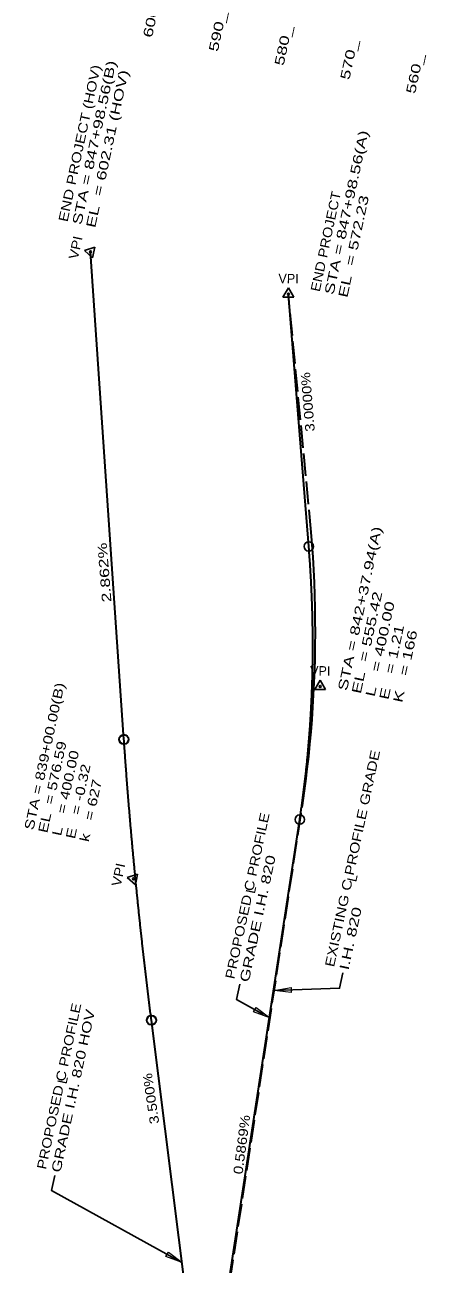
# Model space of a CAD drawing. Extents: x 2363411 to 2369702, y 6977197 to 6988655.
# Drawn here: x 2367365 to 2367963, y 6983553 to 6985397 of the extents above; entities that cross this region are included whole.
import ezdxf
from ezdxf.enums import TextEntityAlignment as Align

# ---------------------------------------------------------------- set-up
doc = ezdxf.new("R2010")
doc.units = 0
doc.header["$LTSCALE"] = 5.6
doc.linetypes.add('LONG_DASHED', pattern=[7.5, 6, -1.5])
for name, color, linetype, lineweight in [('44', 7, 'Continuous', 25), ('58', 7, 'Continuous', 25), ('61', 7, 'Continuous', 25)]:
    doc.layers.add(name, color=color, linetype=linetype, lineweight=lineweight)
doc.layers.add('50', color=7, linetype='Continuous')

msp = doc.modelspace()

# ---------------------------------------------------------------- linework, layer by layer
at = {"layer": '44'}
for p, q in [((2367454.227, 6985060.892), (2367469.602, 6985065.858)), ((2367466.212, 6985050.057), (2367469.602, 6985065.858)), ((2367454.227, 6985060.892), (2367466.212, 6985050.057)), ((2367757.608, 6985005.409), (2367749.412, 6984991.485)), ((2367749.412, 6984991.485), (2367765.572, 6984991.35)), ((2367757.608, 6985005.409), (2367765.572, 6984991.35)), ((2367804.816, 6984422.007), (2367796.685, 6984408.047)), ((2367804.816, 6984422.007), (2367812.845, 6984407.989)), ((2367796.685, 6984408.047), (2367812.845, 6984407.989))]:
    msp.add_line(p, q, dxfattribs=at)
at = {"layer": '44', "lineweight": 35}
for p, q in [((2367512.9, 6984334.011), (2367463.348, 6985058.925)), ((2367787.84, 6984620.829), (2367757.481, 6984996.078)), ((2367604.934, 6983107.709), (2367774.368, 6984214.683)), ((2367609.745, 6983474.807), (2367553.751, 6983916.249))]:
    msp.add_line(p, q, dxfattribs=at)
at = {"layer": '44', "linetype": 'LONG_DASHED', "lineweight": 35}
for points in [[(2367778.265, 6984235.836), (2367780.917, 6984253.937), (2367783.373, 6984272.077), (2367785.633, 6984290.26), (2367787.697, 6984308.486), (2367789.566, 6984326.753), (2367791.24, 6984345.062), (2367792.718, 6984363.412), (2367794, 6984381.804), (2367795.087, 6984400.238), (2367795.977, 6984418.714), (2367796.647, 6984436.432), (2367796.647, 6984436.432), (2367797.155, 6984454.991), (2367797.469, 6984473.591), (2367797.585, 6984492.232), (2367797.507, 6984510.916), (2367797.232, 6984529.641), (2367796.763, 6984548.409), (2367796.098, 6984567.218), (2367795.237, 6984586.067), (2367794.181, 6984604.96), (2367792.929, 6984623.894), (2367791.548, 6984642.045), (2367757.52, 6984996.07)], [(2367626.232, 6983236.018), (2367778.265, 6984235.836), (2367778.265, 6984235.836)]]:
    msp.add_lwpolyline(points, dxfattribs=at)
at = {"layer": '44'}
for centre, radius in [((2367463.348, 6985058.925), 1.5), ((2367757.521, 6984996.078), 1.5), ((2367787.837, 6984620.83), 7), ((2367804.772, 6984412.677), 1.5), ((2367774.364, 6984214.684), 7)]:
    msp.add_circle(centre, radius, dxfattribs=at)
at = {"layer": '44', "lineweight": 35}
for centre in [(2367512.899, 6984334.012), (2367553.751, 6983916.249)]:
    msp.add_circle(centre, 7, dxfattribs=at)
for points in [[(2367774.368, 6984214.683), (2367775.56, 6984222.609), (2367776.718, 6984230.542), (2367777.836, 6984238.484), (2367778.915, 6984246.434), (2367779.959, 6984254.391), (2367780.963, 6984262.357), (2367781.93, 6984270.329), (2367782.861, 6984278.311), (2367783.752, 6984286.301), (2367784.606, 6984294.299), (2367785.423, 6984302.305), (2367786.201, 6984310.32), (2367786.941, 6984318.342), (2367787.645, 6984326.372), (2367788.311, 6984334.41), (2367788.938, 6984342.457), (2367789.528, 6984350.511), (2367790.081, 6984358.574), (2367790.595, 6984366.645), (2367791.073, 6984374.723), (2367791.511, 6984382.81), (2367791.913, 6984390.905), (2367792.276, 6984399.008), (2367792.602, 6984407.119), (2367792.891, 6984415.238), (2367793.143, 6984423.364), (2367793.355, 6984431.5), (2367793.531, 6984439.643), (2367793.667, 6984447.794), (2367793.768, 6984455.953), (2367793.83, 6984464.12), (2367793.853, 6984472.296), (2367793.841, 6984480.479), (2367793.789, 6984488.671), (2367793.7, 6984496.87), (2367793.575, 6984505.078), (2367793.41, 6984513.294), (2367793.208, 6984521.518), (2367792.968, 6984529.749), (2367792.69, 6984537.989), (2367792.374, 6984546.237), (2367792.022, 6984554.493), (2367791.632, 6984562.757), (2367791.202, 6984571.027), (2367790.736, 6984579.308), (2367790.233, 6984587.596), (2367789.691, 6984595.892), (2367789.113, 6984604.196), (2367788.496, 6984612.508), (2367787.84, 6984620.829)], [(2367553.751, 6983916.249), (2367552.689, 6983924.657), (2367551.638, 6983933.062), (2367550.597, 6983941.465), (2367549.565, 6983949.866), (2367548.544, 6983958.265), (2367547.532, 6983966.662), (2367546.53, 6983975.056), (2367545.538, 6983983.449), (2367544.555, 6983991.839), (2367543.584, 6984000.227), (2367542.621, 6984008.614), (2367541.67, 6984016.998), (2367540.729, 6984025.381), (2367539.798, 6984033.761), (2367538.876, 6984042.138), (2367537.964, 6984050.514), (2367537.061, 6984058.887), (2367536.169, 6984067.259), (2367535.288, 6984075.627), (2367534.415, 6984083.994), (2367533.554, 6984092.359), (2367532.703, 6984100.722), (2367531.861, 6984109.082), (2367531.027, 6984117.441), (2367530.205, 6984125.797), (2367529.395, 6984134.151), (2367528.592, 6984142.503), (2367527.799, 6984150.853), (2367527.018, 6984159.2), (2367526.245, 6984167.546), (2367525.484, 6984175.889), (2367524.732, 6984184.23), (2367523.988, 6984192.57), (2367523.256, 6984200.907), (2367522.534, 6984209.242), (2367521.823, 6984217.574), (2367521.12, 6984225.905), (2367520.428, 6984234.236), (2367519.746, 6984242.562), (2367519.073, 6984250.886), (2367518.411, 6984259.208), (2367517.759, 6984267.528), (2367517.117, 6984275.846), (2367516.485, 6984284.162), (2367515.862, 6984292.475), (2367515.249, 6984300.787), (2367514.646, 6984309.096), (2367514.055, 6984317.403), (2367513.471, 6984325.708), (2367512.9, 6984334.011)]]:
    msp.add_spline(points, degree=3, dxfattribs=at)
at = {"layer": '58'}
for p, q in [((2367517.961, 6984128.41), (2367533.322, 6984133.411)), ((2367517.961, 6984128.41), (2367529.969, 6984117.602)), ((2367529.969, 6984117.602), (2367533.322, 6984133.411))]:
    msp.add_line(p, q, dxfattribs=at)
msp.add_circle((2367527.086, 6984126.464), 1.5, dxfattribs=at)
at = {"layer": '61'}
for points in [[(2367736.395, 6983960.488), (2367833.745, 6983964), (2367838.579, 6983986.624)], [(2367720.514, 6983925.077), (2367680.455, 6983947.141), (2367685.289, 6983969.765)], [(2367599.037, 6983556.259), (2367405.316, 6983662.96), (2367410.15, 6983685.584)]]:
    msp.add_lwpolyline(points, dxfattribs=at)
at = {"layer": '61', "lineweight": 13}
for points in [[(2367761.721, 6983957.472), (2367736.31, 6983960.478), (2367761.726, 6983964.951)], [(2367709.46, 6983935.288), (2367729.717, 6983919.655), (2367705.614, 6983928.874)], [(2367579.23, 6983571.612), (2367599.487, 6983555.979), (2367575.384, 6983565.198)]]:
    msp.add_lwpolyline(points, close=True, dxfattribs=at)

# ---------------------------------------------------------------- texts
at = {"layer": '44', "width": 1.45}
for s, p in [('  600_', (2367567.298, 6985435.739)), ('  590_', (2367665.094, 6985414.843)), ('  580_', (2367762.892, 6985393.947)), ('  570_', (2367860.688, 6985373.051)), ('  560_', (2367958.486, 6985352.155))]:
    msp.add_text(s, height=14, rotation=77.939, dxfattribs=at).set_placement(p, align=Align.RIGHT)
at = {"layer": '44'}
for s, rotation, width, p in [('STA = 847+98.56(B)', 77.939, 1.45, (2367449.509, 6985098.236)), ('END PROJECT (HOV)', 77.939, 1.25, (2367428.972, 6985102.624)), ('EL  = 602.31 (HOV)', 77.939, 1.45, (2367470.046, 6985093.848)), ('STA = 847+98.56(A)', 77.939, 1.45, (2367824.566, 6984994.422)), ('END PROJECT', 77.939, 1.15, (2367804.029, 6984998.81)), ('EL  = 572.23', 77.939, 1.45, (2367845.103, 6984990.034)), ('3.0000%', 94.621, 1.2, (2367796.768, 6984792.088)), ('STA = 842+37.94(A)', 77.939, 1.45, (2367844.528, 6984405.315)), ('2.862% ', 94.626, 1.4, (2367494.379, 6984538.372)), ('EL  = 555.42', 77.939, 1.45, (2367865.065, 6984400.927)), ('L   = 400.00', 77.939, 1.45, (2367885.602, 6984396.539)), ('E   = 1.21', 77.939, 1.4, (2367906.14, 6984392.151)), ('K   = 166', 77.939, 1.45, (2367926.677, 6984387.763)), ('STA = 839+00.00(B)', 77.939, 1.3, (2367378.249, 6984198.318)), ('EL  = 576.59', 77.939, 1.3, (2367398.786, 6984193.93)), ('L   = 400.00', 77.939, 1.3, (2367419.323, 6984189.542)), ('E   = -0.32', 77.939, 1.3, (2367439.861, 6984185.154)), ('k   = 627', 77.939, 1.3, (2367460.398, 6984180.766)), ('0.5869%', 82.59, 1.2, (2367689.27, 6983686.556))]:
    msp.add_text(s, height=14, rotation=rotation, dxfattribs=dict(at, width=width)).set_placement(p)
at = {"layer": '44', "width": 1.15}
msp.add_text('VPI', height=14, rotation=77.892, dxfattribs=at).set_placement((2367447.822, 6985063.794), align=Align.CENTER)
at = {"layer": '44'}
for rotation, p in [(359.523, (2367757.715, 6985012.278)), (359.795, (2367804.857, 6984428.878))]:
    msp.add_text('VPI', height=14, rotation=rotation, dxfattribs=at).set_placement(p, align=Align.CENTER)
at = {"layer": '50', "width": 1.2}
msp.add_text('3.500%', height=14, rotation=98.344, dxfattribs=at).set_placement((2367565.513, 6983763.086))
at = {"layer": '58', "width": 1.15}
msp.add_text('VPI', height=14, rotation=78.026, dxfattribs=at).set_placement((2367511.546, 6984131.279), align=Align.CENTER)
at = {"layer": '61'}
for s, width, p in [('EXISTING C PROFILE GRADE', 1.25, (2367825.352, 6983994.6)), ('PROPOSED C PROFILE', 1.2, (2367677.043, 6983976.677)), ('GRADE I.H. 820', 1.4, (2367698.558, 6983972.08)), ('L', 1.05, (2367858.317, 6984121.096)), ('I.H. 820', 1.45, (2367846.867, 6983990.003)), ('PROPOSED C PROFILE', 1.2, (2367396.923, 6983693.56)), ('GRADE I.H. 820 HOV', 1.35, (2367418.438, 6983688.963))]:
    msp.add_text(s, height=14, rotation=77.939, dxfattribs=dict(at, width=width)).set_placement(p)
at = {"layer": '61', "width": 1.05}
for p in [(2367708.694, 6984109.093), (2367428.574, 6983825.976)]:
    msp.add_text('L', height=14, rotation=77.939, dxfattribs=at).set_placement(p, align=Align.CENTER)

doc.saveas('drawing.dxf')
